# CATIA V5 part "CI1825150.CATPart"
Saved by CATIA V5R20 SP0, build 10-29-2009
Part number: CI1825150
Bounding box of the stored display mesh (mm): x -24 to 24, y -19.337 to 184.5, z -31.667 to 27.272
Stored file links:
  C:\Users\Raffaele\Desktop\3D X SITO CF\BOLEX\19-INCLINED ASSEMBLY REF_CI\CI1825150.CATPart

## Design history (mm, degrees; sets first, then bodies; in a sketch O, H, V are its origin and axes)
Set1
  DatumSurface1 to DatumSurface16 "MANIFOLD_SOLID_BREP #393"
  DatumSurface17 to DatumSurface39 "MANIFOLD_SOLID_BREP #1138"
Body1 (main body)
